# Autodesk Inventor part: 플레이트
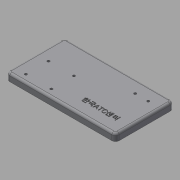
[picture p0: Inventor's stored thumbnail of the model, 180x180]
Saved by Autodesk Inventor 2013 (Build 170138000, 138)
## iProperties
Created: 2018-01
Part Number: 플레이트
Material: 일반
Document SubType Name: Modeling
Designer: mduedu
Density: 1 g/cm^3
Author: mduedu
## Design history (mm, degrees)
sketch "스케치1"
  geometry: L1 (75, 40)-(-75, 40); L2 (-75, 40)-(-75, -40); L3 (-75, -40)-(75, -40); L4 (75, -40)-(75, 40); L5 (75, 40)-(-75, -40); L6 (-75, 40)-(75, -40); 1 further point
  constraints: 12 end point, 2 midpoint, 2 parallel, 1 horizontal, 1 perpendicular
  dimensions: "d0" = 150 distance of L3.end L2.end; "d1" = 80 distance of L2.end L1.end
extrude "돌출1" new body sketch "스케치1" distance "d2" = 10; taper "d3" = 0 deg
fillet "모깎기1" dims "d4" = 5
fillet "모깎기2" dims "d5" = 3
sketch "스케치2"
  geometry: L1 (-70, 40)-(70, 40) reference; L2 (-75, -35)-(-75, 35) reference; 5 further points
  constraints: 2 horizontal alignment, 2 vertical alignment
  dimensions: "d6" = 10 distance from line of point (-58, 30) L1; "d7" = 35 distance of point (-23, 30) point (-58, 30); "d8" = 31 distance of point (-58, -1) point (-58, 30); "d9" = 17 distance from line of point (-58, 30) L2
sketch "스케치3"
  geometry: 4 further points
  constraints: 4 other
hole "구멍1" sketch "스케치3" at (-23, 30), (-58, -1), (-23, -1), (-58, 30) diameter "d10" = 3.4; stored, may be unused: countersink angle "d14" = 90 deg, drill point angle "d16" = 0 deg; dims "d11" = 6, "d12" = 6.5, "d13" = 3.4, "d15" = 8
sketch "스케치4"
  geometry: L1 (75, 35)-(75, -35) reference; L2 (70, -40)-(-70, -40) reference; 3 further points
  constraints: 1 horizontal alignment
  dimensions: "d17" = 17 distance from line of point (58, -22) L1; "d18" = 18 distance of point (40, -22) point (58, -22); "d19" = 18 distance from line of point (58, -22) L2
sketch "스케치5"
  geometry: 2 further points
  constraints: 2 other
hole "구멍2" sketch "스케치5" at (40, -22), (58, -22) diameter "d20" = 3.4; stored, may be unused: countersink angle "d24" = 90 deg, drill point angle "d26" = 0 deg; dims "d21" = 6, "d22" = 6.5, "d23" = 3.4, "d25" = 8
sketch "스케치6"
  geometry: L1 (75, -35)-(75, 35) reference; L2 (-70, -40)-(70, -40) reference; 2 further points
  constraints: 1 other
  dimensions: "d27" = 40 distance from line of point (35, -20) L1; "d28" = 20 distance from line of point (35, -20) L2
feature "엠보싱1" sketch "스케치6" dims "d0" = 150, "d29" = 0.5, "d30" = 0
node "솔리드1"
